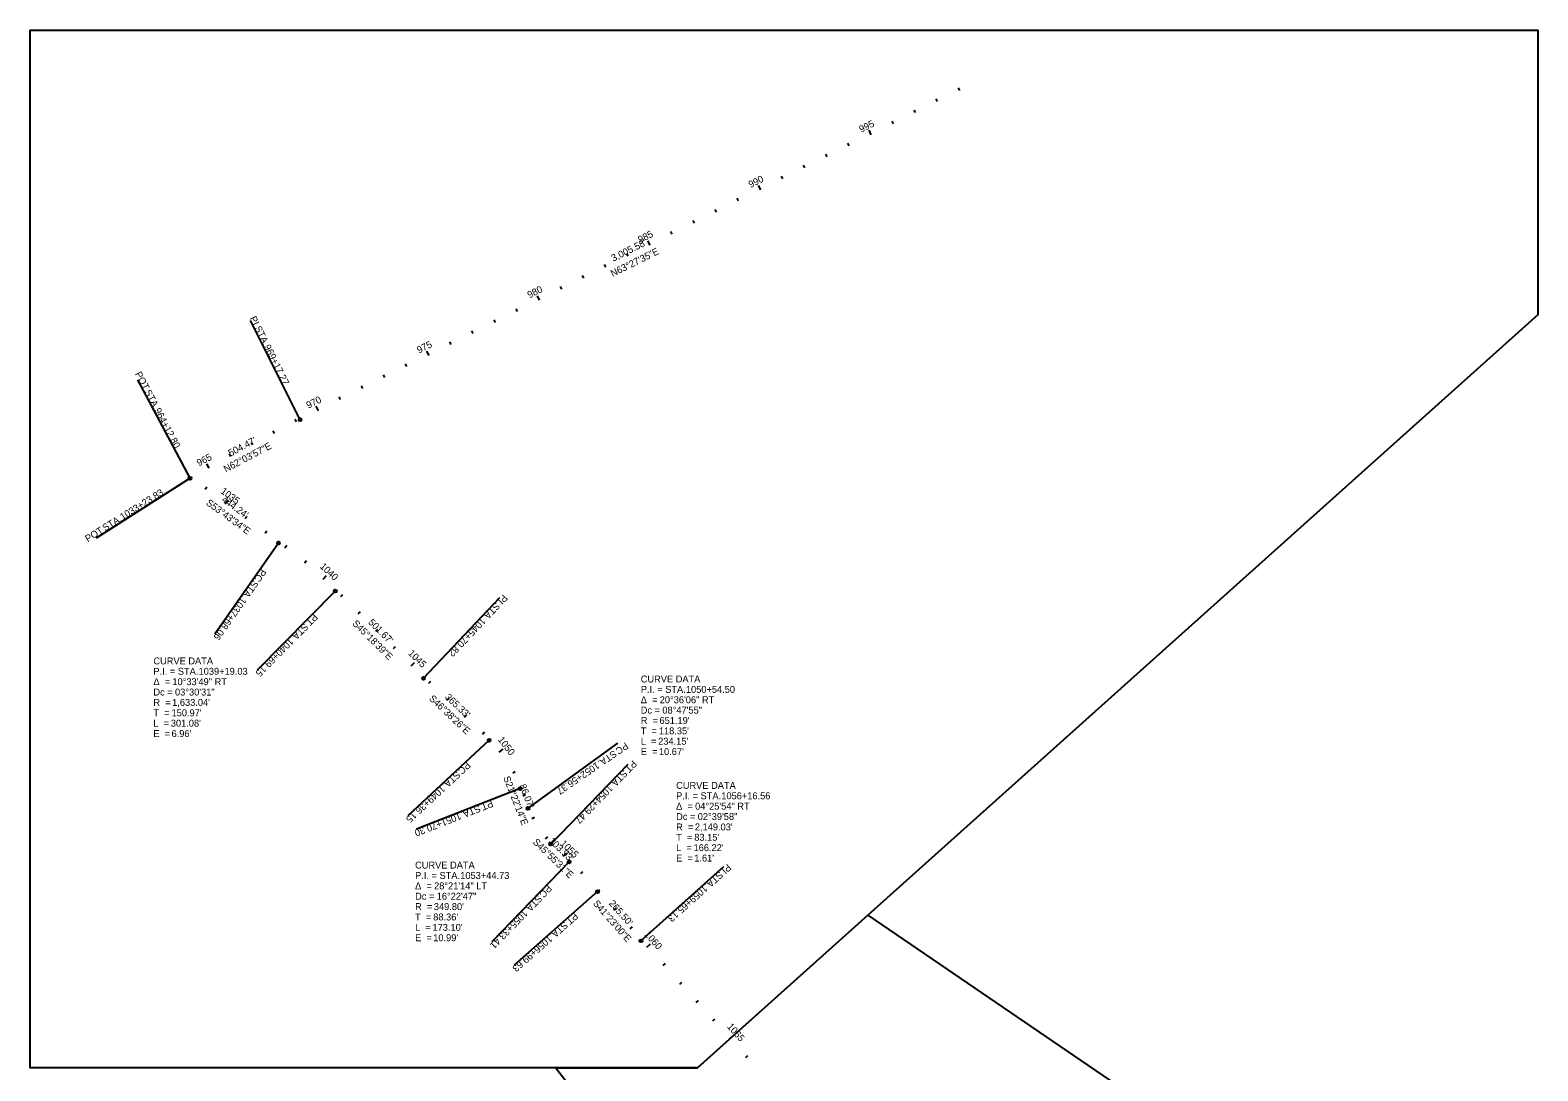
# Model space of a CAD drawing. Extents: x 1845666 to 1851778, y 577180 to 584275.
# Drawn here: x 1845666 to 1851766, y 580062 to 584275 of the extents above; entities that cross this region are included whole.
import ezdxf

# ---------------------------------------------------------------- set-up
doc = ezdxf.new("R2010")
doc.units = 0
for name, color, linetype in [('GE_P_Alignment_500_Bearings', 7, 'Continuous'), ('GE_P_Alignment_500_Cardinal_Points', 7, 'Continuous'), ('GE_P_Alignment_500_Curve_Data', 7, 'Continuous'), ('GE_P_Alignment_500_Distances', 7, 'Continuous'), ('GE_P_Alignment_500_Stations', 7, 'Continuous'), ('SC_Scratch1', 7, 'Continuous')]:
    doc.layers.add(name, color=color, linetype=linetype)

msp = doc.modelspace()

# ---------------------------------------------------------------- linework, layer by layer
at = {"layer": 'GE_P_Alignment_500_Cardinal_Points'}
for p, q in [((1846758.8, 582697.3), (1846557.7, 583099.9)), ((1846313.1, 582461), (1846102.3, 582858.5)), ((1846313.1, 582461), (1845933.8, 582218.7)), ((1846671.2, 582198.1), (1846413.5, 581829.2)), ((1846900.8, 582004), (1846584.3, 581684.1)), ((1847257.5, 581651.2), (1847566.4, 581978.4)), ((1847523.1, 581400.4), (1847193.8, 581093.7)), ((1847680.3, 581124), (1848044.2, 581388.7)), ((1847772.3, 580979.7), (1848085.3, 581303)), ((1847648.8, 581204.3), (1847229.7, 581040.3)), ((1847846.9, 580907.4), (1847534.4, 580583.7)), ((1848137.5, 580588.2), (1848472.5, 580888.6)), ((1847961.9, 580787.4), (1847624.3, 580489.9))]:
    msp.add_line(p, q, dxfattribs=at)
for centre in [(1846758.8, 582697.3), (1846313.1, 582461), (1846313.1, 582461), (1846671.2, 582198.1), (1846900.8, 582004), (1847257.5, 581651.2), (1847523.1, 581400.4), (1847648.8, 581204.3), (1847680.3, 581124), (1847772.3, 580979.7), (1847846.9, 580907.4), (1847961.9, 580787.4), (1848137.5, 580588.2)]:
    msp.add_circle(centre, 6, dxfattribs=at)
at = {"layer": 'GE_P_Alignment_500_Stations'}
for p, q in [((1849427.2, 584030), (1849421.8, 584040.8)), ((1849337.7, 583985.4), (1849332.4, 583996.1)), ((1849158.8, 583896), (1849153.4, 583906.7)), ((1849248.3, 583940.7), (1849242.9, 583951.4)), ((1849069.3, 583851.3), (1849060.4, 583869.2)), ((1848890.4, 583762), (1848885.1, 583772.7)), ((1848979.9, 583806.6), (1848974.5, 583817.4)), ((1848801, 583717.3), (1848795.6, 583728)), ((1848711.5, 583672.6), (1848706.1, 583683.3)), ((1848532.6, 583583.2), (1848527.2, 583594)), ((1848622, 583627.9), (1848613.1, 583645.8)), ((1848443.1, 583538.5), (1848437.7, 583549.3)), ((1848353.6, 583493.9), (1848348.3, 583504.6)), ((1848174.7, 583404.5), (1848165.8, 583422.4)), ((1848264.2, 583449.2), (1848258.8, 583459.9)), ((1848085.3, 583359.8), (1848079.9, 583370.5)), ((1847995.8, 583315.1), (1847990.4, 583325.9)), ((1847816.9, 583225.8), (1847811.5, 583236.5)), ((1847906.3, 583270.4), (1847901, 583281.2)), ((1847727.4, 583181.1), (1847718.5, 583199)), ((1847548.5, 583091.7), (1847543.1, 583102.4)), ((1847637.9, 583136.4), (1847632.6, 583147.1)), ((1847459, 583047), (1847453.7, 583057.8)), ((1847369.6, 583002.3), (1847364.2, 583013.1)), ((1847190.6, 582913), (1847185.3, 582923.7)), ((1847280.1, 582957.7), (1847271.2, 582975.6)), ((1847101.2, 582868.3), (1847095.8, 582879)), ((1847011.7, 582823.6), (1847006.3, 582834.4)), ((1846832.8, 582734.3), (1846823.9, 582752.1)), ((1846922.2, 582778.9), (1846916.9, 582789.7)), ((1846743.5, 582689.2), (1846737.9, 582699.8)), ((1846655.2, 582642.4), (1846649.5, 582653)), ((1846478.5, 582548.7), (1846472.8, 582559.3)), ((1846566.8, 582595.5), (1846561.2, 582606.1)), ((1846390.1, 582501.8), (1846380.8, 582519.5)), ((1846374.5, 582415.9), (1846381.6, 582425.6)), ((1846455.1, 582356.7), (1846466.9, 582372.9)), ((1846535.7, 582297.6), (1846542.8, 582307.2)), ((1846616.4, 582238.4), (1846623.5, 582248.1)), ((1846697.2, 582179.6), (1846704.3, 582189.3)), ((1846776.2, 582118.3), (1846783.9, 582127.5)), ((1846851.3, 582052.3), (1846865, 582066.9)), ((1846922.7, 581982.3), (1846931.2, 581990.8)), ((1846993.8, 581912), (1847002.3, 581920.5)), ((1847064.9, 581841.7), (1847073.4, 581850.2)), ((1847136, 581771.3), (1847144.5, 581779.9)), ((1847207.1, 581701), (1847221.2, 581715.2)), ((1847278.7, 581631.2), (1847286.9, 581639.9)), ((1847351.4, 581562.5), (1847359.6, 581571.2)), ((1847424.1, 581493.8), (1847432.3, 581502.6)), ((1847496.8, 581425.2), (1847505, 581433.9)), ((1847564.2, 581351.6), (1847580.1, 581363.7)), ((1847618.6, 581267.8), (1847629.1, 581273.5)), ((1847659.6, 581176.7), (1847670.8, 581181)), ((1847696.4, 581083.7), (1847707.2, 581088.9)), ((1847751.7, 581000.8), (1847760.6, 581008.8)), ((1847822.9, 580930.6), (1847836.9, 580945)), ((1847894.1, 580860.4), (1847902.7, 580868.8)), ((1847962.2, 580787.2), (1847971.2, 580795.1)), ((1848028.3, 580712.1), (1848037.3, 580720.1)), ((1848094.4, 580637.1), (1848103.4, 580645)), ((1848160.7, 580562.3), (1848175.6, 580575.6)), ((1848227.5, 580487.8), (1848236.4, 580495.8)), ((1848294.2, 580413.3), (1848303.2, 580421.3)), ((1848361, 580338.9), (1848369.9, 580346.9)), ((1848427.7, 580264.4), (1848436.7, 580272.4)), ((1848494.5, 580189.9), (1848509.4, 580203.3)), ((1848561.2, 580115.5), (1848570.2, 580123.5))]:
    msp.add_line(p, q, dxfattribs=at)
at = {"layer": 'SC_Scratch1'}
for p, q in [((1851766.2, 583122.6), (1848365.9, 580074.7)), ((1849977.1, 577272.2), (1847791.3, 580074.7))]:
    msp.add_line(p, q, dxfattribs=at)
for points in [[(1848365.9, 580074.7), (1845666.2, 580074.7), (1845666.2, 584274.7), (1851766.2, 584274.7), (1851766.2, 583122.6)], [(1847791.3, 580074.7), (1848365.9, 580074.7), (1849055, 580692.4)], [(1849055, 580692.4), (1851759.8, 578846), (1851393, 578376.5)]]:
    msp.add_lwpolyline(points, dxfattribs=at)

# ---------------------------------------------------------------- texts
at = {"layer": 'GE_P_Alignment_500_Bearings'}
for s, rotation, p in [('N63°27\'35"E', 26.54024, (1848023, 583275.1)), ('N62°03\'57"E', 27.93413, (1846458, 582483.5)), ('S53°43\'34"E', 323.72602, (1846375.6, 582355.6)), ('S45°18\'39"E', 315.31074, (1846967.6, 581870.4)), ('S46°38\'26"E', 316.64047, (1847277.8, 581566)), ('S21°22\'14"E', 291.37063, (1847579.9, 581248.6)), ('S45°55\'31"E', 315.92542, (1847697.6, 580985.2)), ('S41°23\'00"E', 311.38333, (1847941.4, 580738.2))]:
    msp.add_text(s, height=28, rotation=rotation, dxfattribs=at).set_placement(p)
at = {"layer": 'GE_P_Alignment_500_Cardinal_Points'}
for s, rotation, p in [('PI', 296.54024, (1846553.8, 583108.7)), (' STA. ', 296.54024, (1846568.9, 583078.3)), ('969+17.27', 296.54024, (1846611.2, 582993.8)), ('POT', 297.93413, (1846089.5, 582883.5)), (' STA. ', 297.93413, (1846123.3, 582819.8)), ('964+12.80', 297.93413, (1846167.5, 582736.3)), ('1033+23.83', 32.17186, (1846040.4, 582289.9)), ('POT', 32.17186, (1845899.4, 582201.3)), (' STA. ', 32.17186, (1845960.4, 582239.6)), ('PC', 235.06458, (1846600.7, 582096.4)), (' STA. ', 235.06458, (1846574.4, 582058.8)), ('1037+68.06', 235.06458, (1846520.3, 581981.3)), (' STA. ', 226.64047, (1847556.8, 581967.6)), ('PI', 226.64047, (1847580.1, 581992.2)), ('PT', 225.31074, (1846813.1, 581914.7)), ('1045+70.82', 226.64047, (1847491.9, 581898.8)), (' STA. ', 225.31074, (1846782, 581883.3)), ('1040+69.15', 225.31074, (1846715.6, 581816.1)), ('PC', 214.37148, (1848073.9, 581393)), (' STA. ', 214.37148, (1848036.1, 581367.1)), (' STA. ', 222.96485, (1847398.8, 581284.1)), ('PC', 222.96485, (1847432.4, 581315.3)), ('1052+56.37', 214.37148, (1847958, 581313.7)), (' STA. ', 225.92542, (1848072.9, 581289.6)), ('PT', 225.92542, (1848103.6, 581321.3)), ('1049+36.15', 222.96485, (1847329.7, 581219.6)), ('1054+29.47', 225.92542, (1848007.2, 581221.7)), ('PT', 201.37063, (1847532.7, 581158.5)), ('1051+70.30', 201.37063, (1847403.6, 581107.9)), (' STA. ', 201.37063, (1847491.6, 581142.4)), (' STA. ', 221.8718, (1848462, 580878.6)), ('PI', 221.8718, (1848487.3, 580901.2)), ('PC', 226.00405, (1847759.8, 580816.6)), ('1059+65.13', 221.8718, (1848391.6, 580815.5)), (' STA. ', 226.00405, (1847728, 580783.6)), ('1055+33.41', 226.00405, (1847662.3, 580715.6)), (' STA. ', 221.38333, (1847834.9, 580675)), ('PT', 221.38333, (1847868, 580704.1)), ('1056+99.63', 221.38333, (1847764, 580612.5))]:
    msp.add_text(s, height=28, rotation=rotation, dxfattribs=at).set_placement(p)
at = {"layer": 'GE_P_Alignment_500_Curve_Data'}
for s, p in [('CURVE DATA', (1846164.8, 581707.3)), ('Δ  = ', (1846164.8, 581623.3)), ('P.I. = STA. ', (1846164.8, 581665.3)), ('10°33\'49" RT', (1846241.6, 581623.3)), ('1039+19.03', (1846347.5, 581665.3)), ('CURVE DATA', (1848136.6, 581634.1)), ('Dc = ', (1846164.8, 581581.3)), ('03°30\'31"', (1846252.2, 581581.3)), ('Δ  = ', (1848136.6, 581550.1)), ('P.I. = STA. ', (1848136.6, 581592.1)), ('20°36\'06" RT', (1848213.3, 581550.1)), ('1050+54.50', (1848319.2, 581592.1)), ('T  = ', (1846164.8, 581497.3)), ('R  = ', (1846164.8, 581539.3)), ("150.97'", (1846238.2, 581497.3)), ("1,633.04'", (1846240.7, 581539.3)), ('Dc = ', (1848136.6, 581508.1)), ('08°47\'55"', (1848224, 581508.1)), ('L  = ', (1846164.8, 581455.3)), ("301.08'", (1846235.2, 581455.3)), ('T  = ', (1848136.6, 581424.1)), ('R  = ', (1848136.6, 581466.1)), ("118.35'", (1848209.9, 581424.1)), ("651.19'", (1848212.4, 581466.1)), ('E  = ', (1846164.8, 581413.3)), ("6.96'", (1846238.2, 581413.3)), ('L  = ', (1848136.6, 581382.1)), ("234.15'", (1848207, 581382.1)), ('E  = ', (1848136.6, 581340.1)), ("10.67'", (1848210, 581340.1)), ('CURVE DATA', (1848279.7, 581203.3)), ('Δ  = ', (1848279.7, 581119.3)), ('P.I. = STA. ', (1848279.7, 581161.3)), ('04°25\'54" RT', (1848356.5, 581119.3)), ('1056+16.56', (1848462.4, 581161.3)), ('Dc = ', (1848279.7, 581077.3)), ('02°39\'58"', (1848367.1, 581077.3)), ('R  = ', (1848279.7, 581035.3)), ("2,149.03'", (1848355.5, 581035.3)), ('T  = ', (1848279.7, 580993.3)), ('L  = ', (1848279.7, 580951.3)), ("166.22'", (1848350.1, 580951.3)), ("83.15'", (1848353.1, 580993.3)), ('CURVE DATA', (1847223.6, 580880.8)), ('E  = ', (1848279.7, 580909.3)), ("1.61'", (1848353.1, 580909.3)), ('P.I. = STA. ', (1847223.6, 580838.8)), ('1053+44.73', (1847406.2, 580838.8)), ('Δ  = ', (1847223.6, 580796.8)), ('Dc = ', (1847223.6, 580754.8)), ('28°21\'14" LT', (1847300.3, 580796.8)), ('16°22\'47"', (1847311, 580754.8)), ('R  = ', (1847223.6, 580712.8)), ("349.80'", (1847299.4, 580712.8)), ('T  = ', (1847223.6, 580670.8)), ("88.36'", (1847297, 580670.8)), ('L  = ', (1847223.6, 580628.8)), ('E  = ', (1847223.6, 580586.8)), ("173.10'", (1847294, 580628.8)), ("10.99'", (1847297, 580586.8))]:
    msp.add_text(s, height=28, dxfattribs=at).set_placement(p)
at = {"layer": 'GE_P_Alignment_500_Distances'}
for s, rotation, p in [("3,005.58'", 26.54024, (1848025.7, 583337)), ("504.47'", 27.93413, (1846476.7, 582548.2)), ("444.24'", 323.72602, (1846438.4, 582369.2)), ("501.67'", 315.31074, (1847031.9, 581874.9)), ("365.33'", 316.64047, (1847342, 581571.9)), ("86.07'", 291.37063, (1847644.6, 581216.2)), ("103.93'", 315.92542, (1847761.9, 580990.3)), ("265.50'", 311.38333, (1848005.9, 580738.2))]:
    msp.add_text(s, height=28, rotation=rotation, dxfattribs=at).set_placement(p)
at = {"layer": 'GE_P_Alignment_500_Stations'}
for s, rotation, p in [('995', 26.54024, (1849028.6, 583858.9)), ('990', 26.54024, (1848580.9, 583635.3)), ('985', 26.54024, (1848134, 583412.1)), ('980', 26.54024, (1847686.3, 583188.5)), ('975', 26.54024, (1847239.4, 582965.3)), ('970', 26.54024, (1846791.7, 582741.7)), ('965', 27.93413, (1846349.2, 582508.4)), ('1035', 323.72602, (1846434.3, 582403)), ('1040', 316.92693, (1846835.8, 582101)), ('1045', 315.31074, (1847193.3, 581749.9)), ('1050', 307.34719, (1847557, 581402.2)), ('1055', 315.92542, (1847808.6, 580979.4)), ('1060', 311.8718, (1848149.6, 580612.2)), ('1065', 311.8718, (1848483.6, 580239.6))]:
    msp.add_text(s, height=28, rotation=rotation, dxfattribs=at).set_placement(p)

doc.saveas('drawing.dxf')
